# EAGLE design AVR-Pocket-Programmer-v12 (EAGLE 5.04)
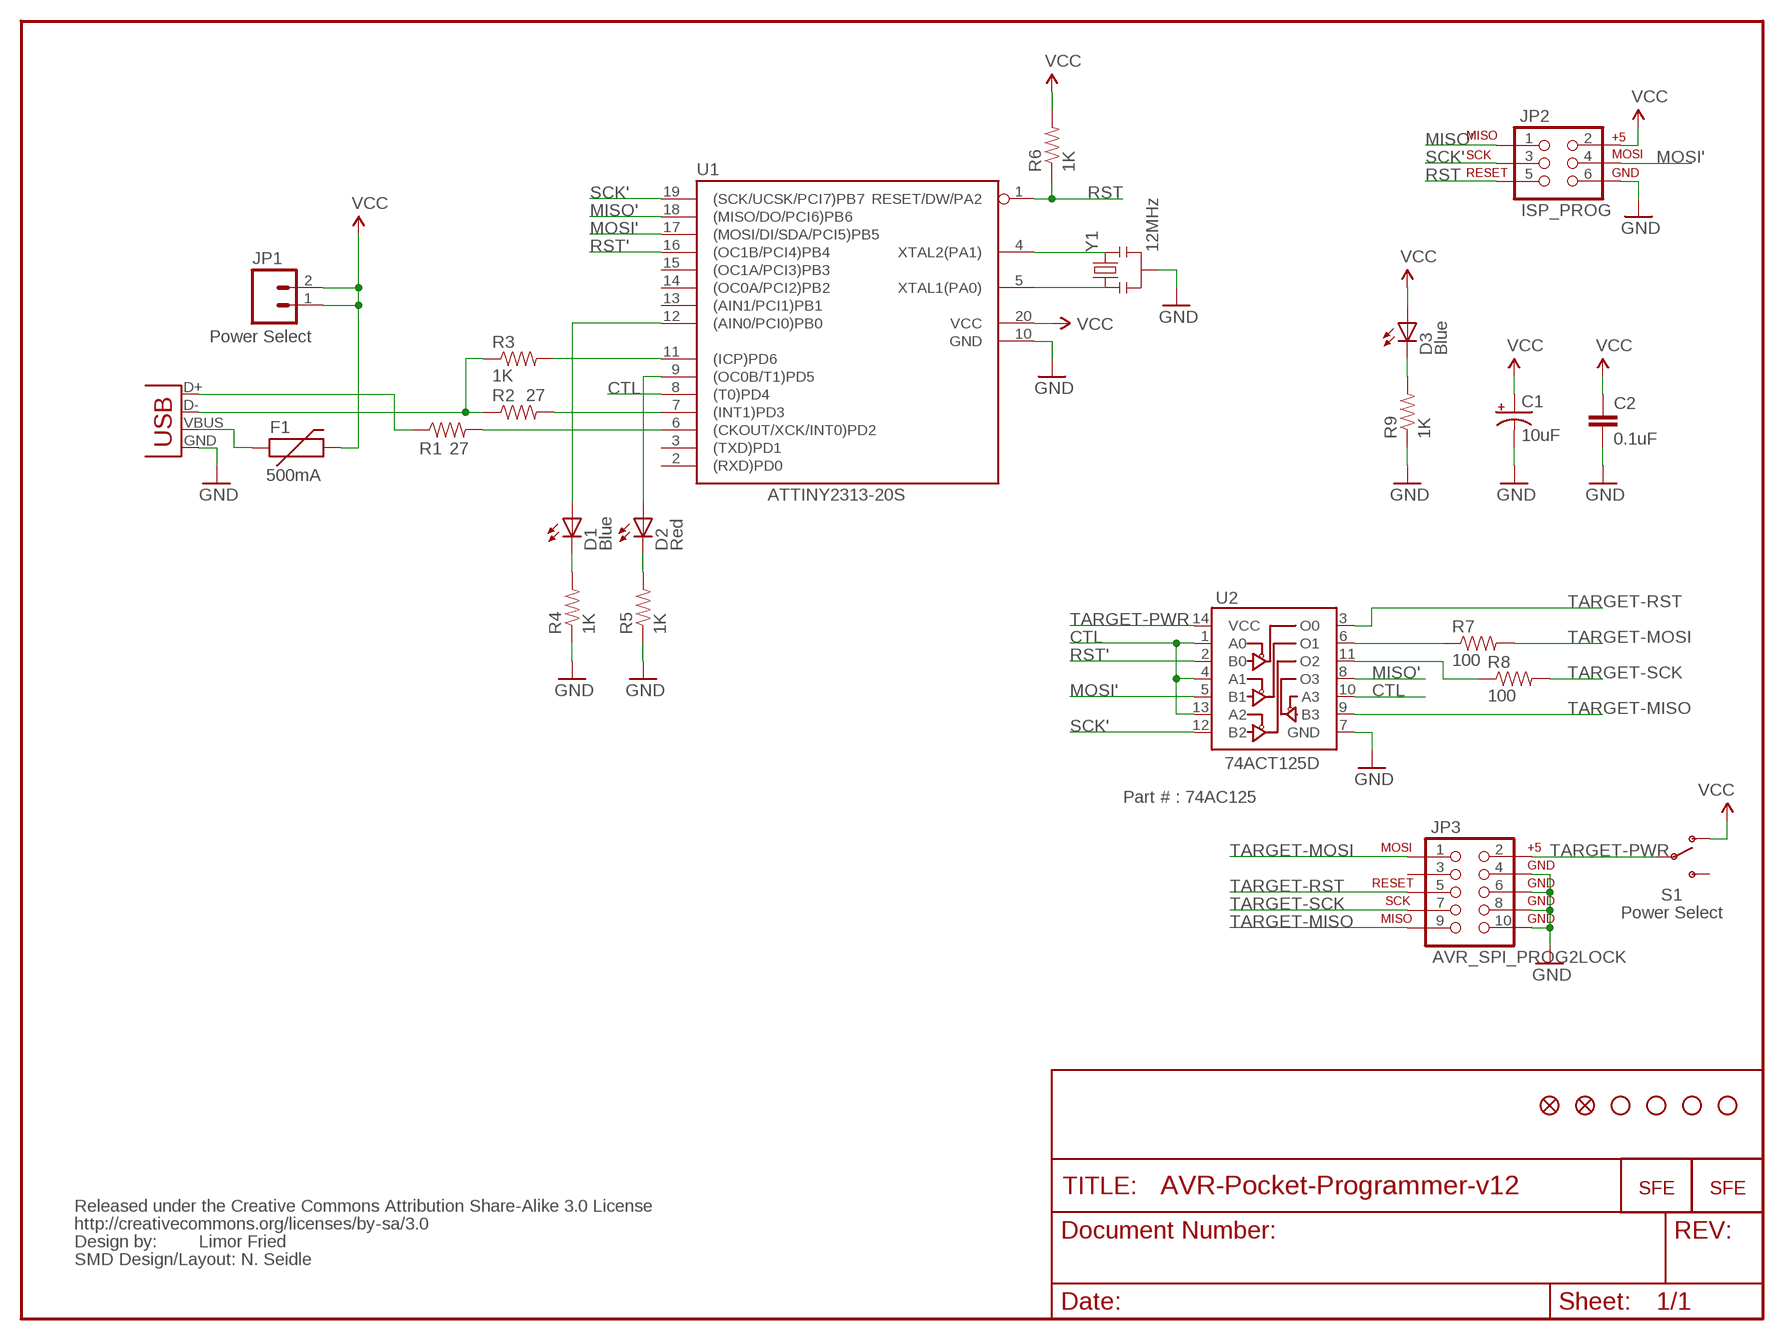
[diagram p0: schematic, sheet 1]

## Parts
C1  10uF  CAP_POL1206  [EIA3216]
C2  0.1uF  CAP0402-CAP  [0402-CAP]
D1  Blue  LED0603  [LED-0603]
D2  Red  LED0603  [LED-0603]
D3  Blue  LED0603  [LED-0603]
F1  500mA  PTCSMD  [PTC-1206]
JP1  Power Select  M02PTH  [1X02]
JP2  ISP_PROG  AVR_SPI_PRG_6PTH  [2X3]
JP3  AVR_SPI_PROG2LOCK  [2X5-SHROUDED_LOCK]
R1  27  RESISTOR0402-RES  [0402-RES]
R2  27  RESISTOR0402-RES  [0402-RES]
R3  1K  RESISTOR0402-RES  [0402-RES]
R4  1K  RESISTOR0402-RES  [0402-RES]
R5  1K  RESISTOR0402-RES  [0402-RES]
R6  1K  RESISTOR0402-RES  [0402-RES]
R7  100  RESISTOR0402-RES  [0402-RES]
R8  100  RESISTOR0402-RES  [0402-RES]
R9  1K  RESISTOR0402-RES  [0402-RES]
S1  Power Select  SWITCH-SPSTSMD  [AYZ0202]
U1  ATTINY2313-20S  [SO20L]
U2  74ACT125D  [SO014]
U$1  STAND-OFF  [STAND-OFF]
U$2  LOGO-SFESK  [SFE-LOGO-FLAME]
U$3  STAND-OFF  [STAND-OFF]
U$4  STAND-OFF  [STAND-OFF]
U$5  STAND-OFF  [STAND-OFF]
U$6  FIDUCIAL1X2  [FIDUCIAL-1X2]
U$7  FIDUCIAL1X2  [FIDUCIAL-1X2]
U$8  LOGO-SFENEW  [SFE-NEW-WEBLOGO]
U$9  CREATIVE_COMMONS  [CREATIVE_COMMONS]
X2  USBSMD  [USB-MINIB]
Y1  12MHz  RESONATORSMD  [RESONATOR-SMD]

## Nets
CTL: U1.8((T0)PD4) U2.1(A0) U2.4(A1) U2.10(A3) U2.13(A2)
D+: R1.1 X2.D+
D-: R2.1 R3.1 X2.D-
GND: C1.C(-) C2.2 JP2.6 JP3.4 JP3.6 JP3.8 JP3.10 R4.1 R5.1 R9.1 U1.10(GND) U2.7(GND) X2.GND Y1.2
MISO': JP2.1 U1.18((MISO/DO/PCI6)PB6) U2.8(O3)
MOSI': JP2.4 U1.17((MOSI/DI/SDA/PCI5)PB5) U2.5(B1)
N$1: R3.2 U1.11((ICP)PD6)
N$2: D2.A U1.9((OC0B/T1)PD5)
N$3: D3.C R9.2
N$4: F1.1 X2.VBUS
N$17: D1.A U1.12((AIN0/PCI0)PB0)
N$18: D1.C R4.2
N$19: D2.C R5.2
N$20: U1.4(XTAL2(PA1)) Y1.3
N$21: U1.5(XTAL1(PA0)) Y1.1
N$22: R7.1 U2.6(O1)
N$25: R8.1 U2.11(O2)
PD+: R1.2 U1.6((CKOUT/XCK/INT0)PD2)
PD-: R2.2 U1.7((INT1)PD3)
RST: JP2.5 R6.1 U1.1(RESET/DW/PA2)
RST': U1.16((OC1B/PCI4)PB4) U2.2(B0)
SCK': JP2.3 U1.19((SCK/UCSK/PCI7)PB7) U2.12(B2)
TARGET-MISO: JP3.9 U2.9(B3)
TARGET-MOSI: JP3.1 R7.2
TARGET-PWR: JP3.2 S1.2(P) U2.14(VCC)
TARGET-RST: JP3.5 U2.3(O0)
TARGET-SCK: JP3.7 R8.2
VCC: C1.A(+) C2.1 D3.A F1.2 JP1.1 JP1.2 JP2.2 R6.2 S1.1(O) U1.20(VCC)
Unconnected: JP3.3 S1.3(S) U1.2((RXD)PD0) U1.3((TXD)PD1) U1.13((AIN1/PCI1)PB1) U1.14((OC0A/PCI2)PB2) U1.15((OC1A/PCI3)PB3)

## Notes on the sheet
- Part # : 74AC125
- Limor Fried
- SMD Design/Layout: N. Seidle

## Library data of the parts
C1 = SparkFun:CAP_POL: Capacitor Polarized
C2 = SparkFun:CAP: Capacitor
D1-D3 = SparkFun:LED: LEDs
F1 = SparkFun:PTC: Resettable Fuse PTC
JP1 = SparkFun:M02: Header 2
JP2 = SparkFun:AVR_SPI_PRG_6: AVR ISP 6 Pin This is the reduced ISP connector for AVR programming. Common on Arduino. This footprint will take up less PCB space and can be used with a 10-pin to 6-pin adapter such as SKU: BOB-08508
JP3 = SparkFun:AVR_SPI_PROG2: AVR ICSP Header This is the standard AVR In Circuit Serial Programming header. Minimal, but includes pin one indicator. Works with standard Olimex programmers. Also look for the 6-pin reduced version. Spark Fun Electronics SKU: PRT-00778
R1-R9 = SparkFun:RESISTOR: Resistor
S1 = SparkFun:SWITCH-SPST: SPST Switch Simple slide switch. Spark Fun Electronics SKU : COM-00102
U1 = avr:ATTINY2313: MICROCONTROLLER 2 Kbytes FLASH 128 bytes SRAM 128 bytes EEPROM USART USI
U2 = SparkFun:74ACT125D: Quad Buffer with 3-State Outputs- ON Semi Conductor: Digikey P/N MC74ACT125DR2GOSTR-ND
U$1 U$3-U$5 = SparkFun:STAND-OFF: Stand Off
U$2 U$8 = SparkFun:LOGO-SFE: Spark Fun Electronics PCB Logo
U$6 U$7 = SparkFun:FIDUCIAL: Fiducial Alignment Points
U$9 = SparkFun:CREATIVE_COMMONS
X2 = SparkFun:USB: USB Connectors USB-B-PTH is fully proven SKU : PRT-00139 USB-miniB is fully proven SKU : PRT-00587 USB-A-PCB is untested. USB-A-H is throughly reviewed, but untested. Spark Fun Electronics SKU : PRT-00437 USB-B-SMT is throughly reviewed, but untested. Needs silkscreen touching up. USB-A-S has not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
Y1 = SparkFun:RESONATOR: Resonator Small SMD resonator. This is the itty bitty 10/20MHz resonators with built in caps. CSTCE10M0G55 and CSTCE20M0V53. Footprint has been reviewed closely but hasn't been tested yet.

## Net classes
0 default: width 0.203 mm, drill 0.508 mm, clearance 0.203 mm

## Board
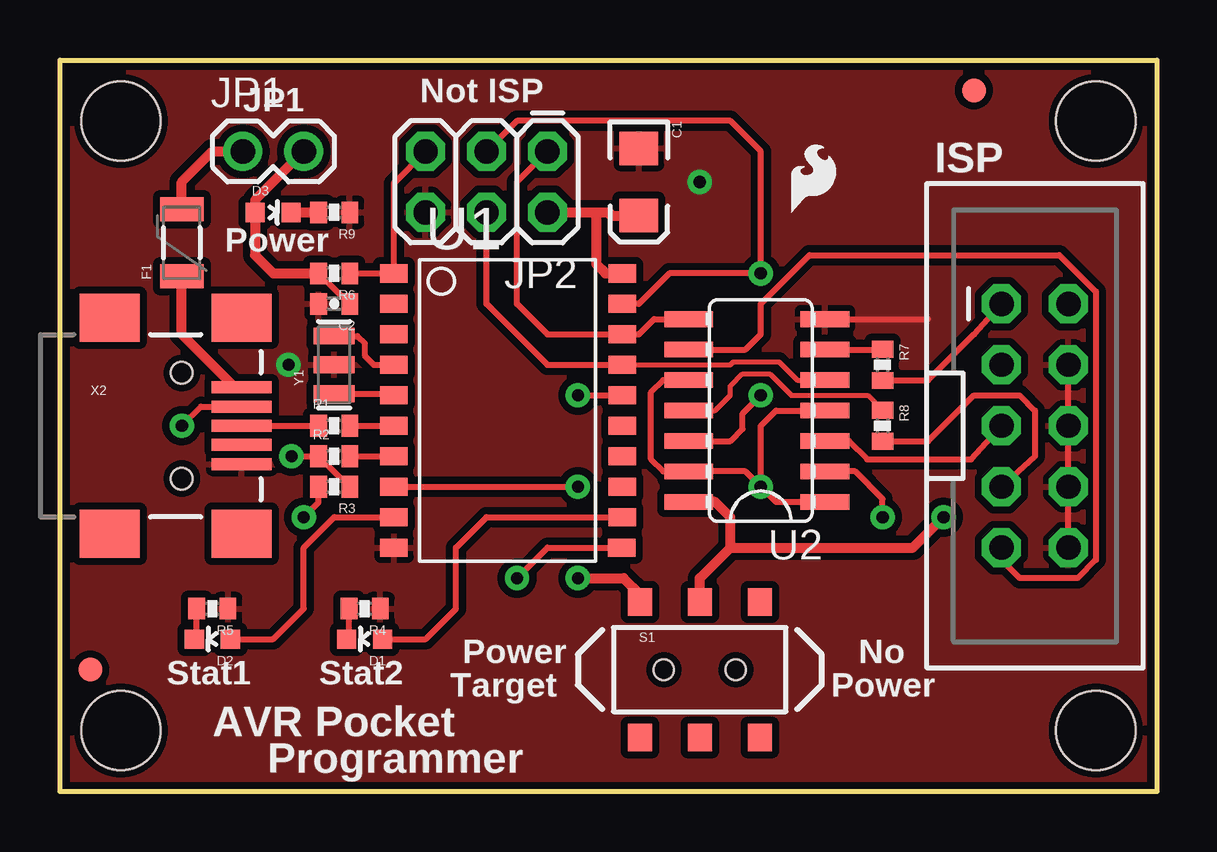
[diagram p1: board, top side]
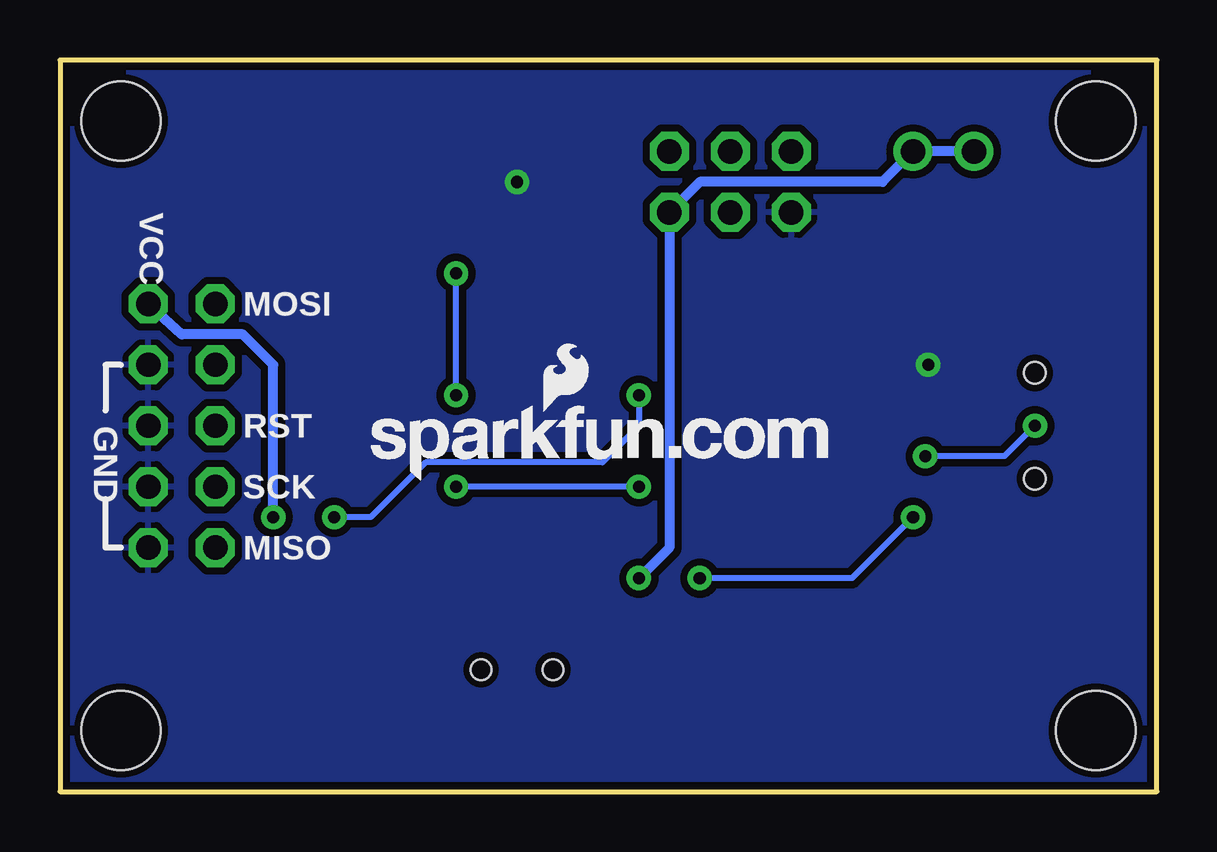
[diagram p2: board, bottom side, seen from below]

Size 45.72 x 30.48 mm. Coordinates in mm from the lower left corner, seen from the top.
Outline: 0,30.48 45.72,30.48 45.72,0 0,0 0,30.48
Copper layers (1*16): Top 0.035mm / dielectric 1.5mm / Bottom 0.035mm
Design rules "SparkFun": minimum track width 8mil, minimum drill 20mil, track to track 8mil, track to pad 8mil, pad to pad 8mil, via to via 8mil, smd to smd 8mil, copper to edge 10mil, drill to drill 8mil, minimum pad ring 12mil, minimum via ring 10mil, stop-mask expansion 4mil, vias tented up to drill 20mil, thermal gap 10mil

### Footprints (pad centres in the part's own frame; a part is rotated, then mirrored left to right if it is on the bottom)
EIA3216 = smd 1.4 x 1.6: A 1.4,0; C -1.4,0
0402-CAP = smd 0.7 x 0.9: 1 -0.65,0; 2 0.65,0
LED-0603 = smd 0.8 x 0.8: A 0,-0.75; C 0,0.75
PTC-1206 = smd 1 x 1.8: 1 -1.4,0; 2 1.4,0
1X02 = drill 1.016 round: 1 0,0; 2 2.54,0
2X3 = drill 1.016 octagon: 1 0,0; 2 0,2.54; 3 2.54,0; 4 2.54,2.54; 5 5.08,0; 6 5.08,2.54
2X5-SHROUDED_LOCK = drill 1.016 octagon: 1 -1.397,5.08; 2 1.397,5.08; 3 -1.397,2.54; 4 1.397,2.54; 5 -1.397,0; 6 1.397,0; 7 -1.397,-2.54; 8 1.397,-2.54; 9 -1.397,-5.08; 10 1.397,-5.08
0402-RES = smd 0.7 x 0.9: 1 -0.65,0; 2 0.65,0
AYZ0202 = smd 1 x 1.15: 1 -2.5,2.825; 2 0,2.825; 3 2.5,2.825; 4 -2.5,-2.825; 5 0,-2.825; 6 2.5,-2.825 | hole 0.85: 1.5,0; -1.5,0
SO20L = smd 0.762 x 1.143: 1 -5.08,-5.131; 2 -3.81,-5.131; 3 -2.54,-5.131; 4 -1.27,-5.131; 5 0,-5.131; 6 1.27,-5.131; 7 2.54,-5.131; 8 3.81,-5.131; 9 5.08,-5.131; 10 6.35,-5.131; 11 6.35,4.369; 12 5.08,4.394; 13 3.81,4.394; 14 2.54,4.394; 15 1.27,4.394; 16 0,4.394; 17 -1.27,4.394; 18 -2.54,4.394; 19 -3.81,4.394; 20 -5.08,4.394
SO014 = smd 0.66 x 2.032: 1 -3.175,-2.68; 2 -1.905,-2.68; 3 -0.635,-2.68; 4 0.635,-2.68; 5 1.905,-2.68; 6 3.175,-2.68; 7 4.445,-2.68; 8 4.445,2.997; 9 3.175,2.997; 10 1.905,2.997; 11 0.635,2.997; 12 -0.635,2.997; 13 -1.905,2.997; 14 -3.175,2.997
STAND-OFF = hole 3.302: 0,0
FIDUCIAL-1X2 = smd 1 x 1: 1 0,0
USB-MINIB = smd 2.5 x 0.5: D+ 2.5,0; D- 2.5,0.8; GND 2.5,-1.6; ID 2.5,-0.8; VBUS 2.5,1.6 | smd 2.5 x 2: GND@1 -3,-4.5; GND@2 -3,4.5; GND@3 2.5,4.5; GND@4 2.5,-4.5 | hole 0.9: 0,2.2; 0,-2.2
RESONATOR-SMD = smd 0.7 x 1.7: 1 -1.2,0; 2 0,0; 3 1.2,0

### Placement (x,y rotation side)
C1  24.13,25.4 270 top
C2  11.43,20.32 180 top
D1  12.7,6.35 90 top
D2  6.35,6.35 90 top
D3  8.89,24.13 270 top
F1  5.08,22.86 90 top
JP1  7.62,26.67 0 top
JP2  20.32,26.67 180 top
JP3  40.64,15.24 0 top
R1  11.43,15.24 0 top
R2  11.43,13.97 0 top
R3  11.43,12.7 180 top
R4  12.7,7.62 180 top
R5  6.35,7.62 180 top
R6  11.43,21.59 180 top
R7  34.29,17.78 270 top
R8  34.29,15.24 270 top
R9  11.43,24.13 180 top
S1  26.67,5.08 0 top
U1  19.05,16.51 270 top
U2  29.21,15.24 90 top
U$1  2.54,2.54 0 top
U$2  30.48,24.13 0 top
U$3  2.54,27.94 0 top
U$4  43.18,27.94 0 top
U$5  43.18,2.54 0 top
U$6  1.27,5.08 0 top
U$7  38.1,29.21 0 top
U$8  32.77,12.95 0 bottom
U$9  not placed on the board
X2  5.08,15.24 0 top
Y1  11.43,17.78 90 top

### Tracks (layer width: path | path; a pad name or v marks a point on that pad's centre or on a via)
CTL  (via drill 0.51)
  Top 0.254: U2.1 29.84,12.06 v29.21,12.7 | v29.21,12.7 28.57,13.34 U2.13 25.15,13.34 24.64,13.84 24.64,16.64 25.15,17.14 U2.10 | U2.4 29.84,15.88 29.21,15.24 v29.21,12.7 | U1.8 v21.59,12.7
  Bottom 0.254: v21.59,12.7 v29.21,12.7
D+
  Top 0.254: X2.D+ R1.1
D-  (via drill 0.51)
  Top 0.254: R3.1 12.05,12.7 R2.1 v9.65,13.97 | X2.D- 5.88,16.04 v5.08,15.24
  Bottom 0.254: v9.65,13.97 6.35,13.97 v5.08,15.24
GND  (via drill 0.51)
  Top 0.254: U2.7 36.2,19.68 | JP3.4 JP3.6 JP3.8 JP3.10
  other vias: 9.53,17.78 26.67,25.4
  pour Top (isolate 0.305): 0,0 0,30.48 45.72,30.48 45.72,0
  pour Bottom (isolate 0.305): 0,0 0,30.48 45.72,30.48 45.72,0
MISO'
  Top 0.254: JP2.1 19.05,25.4 19.05,20.32 20.32,19.05 U1.18 24.13,19.05 24.77,19.68 U2.8
MOSI'
  Top 0.203: U2.5 30.73,17.14 29.97,17.91 28.07,17.91 27.94,17.78 U1.17
  Top 0.254: U1.17 20.32,17.78 17.78,20.32 JP2.4
N$1  (via drill 0.51)
  Top 0.254: R3.2 10.78,12.05 v10.16,11.43 | v19.05,8.89 20.32,10.16 U1.11
  Bottom 0.254: v19.05,8.89 12.7,8.89 v10.16,11.43
N$2
  Top 0.254: D2.A 8.89,6.35 10.16,7.62 10.16,10.16 11.43,11.43 U1.9
N$3
  Top 0.406: D3.C R9.2
N$4
  Top 0.406: X2.VBUS 7.29,16.84 5.08,19.05 F1.1
N$17
  Top 0.254: D1.A 15.24,6.35 16.51,7.62 16.51,10.16 17.78,11.43 U1.12
N$18
  Top 0.254: R4.2 12.05,6.45 D1.C
N$19
  Top 0.254: R5.2 5.7,6.45 D2.C
N$20
  Top 0.203: U1.4 13.97,17.78
  Top 0.254: U1.4 13.08,17.78 12.7,18.16 12.7,18.67 12.39,18.98 Y1.3
N$21
  Top 0.254: Y1.1 13.85,16.58 U1.5
N$22
  Top 0.254: U2.6 34.27,18.41 R7.1
N$25
  Top 0.203: R8.1 33.67,16.51 30.48,16.51 29.59,17.4 28.45,17.4 27.94,16.89 27.94,16.51 27.3,15.88 U2.11
PD+
  Top 0.254: R1.2 U1.6
PD-
  Top 0.254: R2.2 U1.7
RST
  Top 0.254: R6.1 U1.1 13.92,25.35 JP2.5
RST'  (via drill 0.51)
  Top 0.254: v21.59,16.51 U1.16 | 34.29,11.81 v34.29,11.43 34.29,12.19 33.15,13.34 U2.2
  Bottom 0.254: v34.29,11.43 32.77,11.43 30.48,13.72 23.11,13.72 21.59,15.24 v21.59,16.51
SCK'  (via drill 0.51)
  Top 0.254: JP2.3 19.05,27.94 27.94,27.94 29.21,26.67 v29.21,21.59 25.4,21.59 24.13,20.32 U1.19 | U2.12 27.94,14.61 28.45,15.11 28.45,15.75 v29.21,16.51
  Bottom 0.254: v29.21,16.51 v29.21,21.59
TARGET-MISO
  Top 0.254: U2.9 28.57,18.41 29.21,19.05 29.21,20.32 31.24,22.35 41.66,22.35 43.18,20.83 43.18,9.65 42.42,8.89 40.01,8.89 39.37,9.53 JP3.9
TARGET-MOSI
  Top 0.254: R7.2 36.18,17.13 38.1,19.05 JP3.1
TARGET-PWR  (via drill 0.51)
  Top 0.406: U2.14 27.3,12.06 27.94,11.43 27.94,10.16 | S1.2 26.67,8.89 27.94,10.16 | 27.94,10.16 35.56,10.16 v36.83,11.43
  Bottom 0.406: v36.83,11.43 36.83,17.78 38.1,19.05 40.64,19.05 JP3.2
TARGET-RST
  Top 0.254: U2.3 32.89,14.61 33.66,13.84 37.97,13.84 JP3.5
TARGET-SCK
  Top 0.254: R8.2 36.18,14.59 38.1,16.51 40.01,16.51 40.64,15.88 40.64,13.97 JP3.7
VCC  (via drill 0.51)
  Top 0.254: C2.1 12.05,20.32 R6.2
  Top 0.406: S1.1 24.17,8.21 23.5,8.89 v21.59,8.89 | JP1.2 8.14,24.65 D3.A 8.13,24.12 8.13,22.35 8.89,21.59 R6.2 | F1.2 5.08,25.4 6.35,26.67 JP1.1 | C1.A 22.99,24 22.86,24.13 22.48,24.13 | JP2.2 22.48,24.13 | U1.20 22.73,21.59 22.35,21.97 22.35,24 22.48,24.13
  Bottom 0.406: v21.59,8.89 20.32,10.16 JP2.2 19.05,25.4 11.43,25.4 JP1.2 JP1.1

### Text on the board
tPlace: Not ISP | JP1 | ISP | Power | Power | No | Stat1 | Stat2 | Target | Power | AVR Pocket | Programmer
bPlace: VCC | MOSI | RST | GND | SCK | MISO
Document: Limor Fried | SMD Design/Layout: N. Seidle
